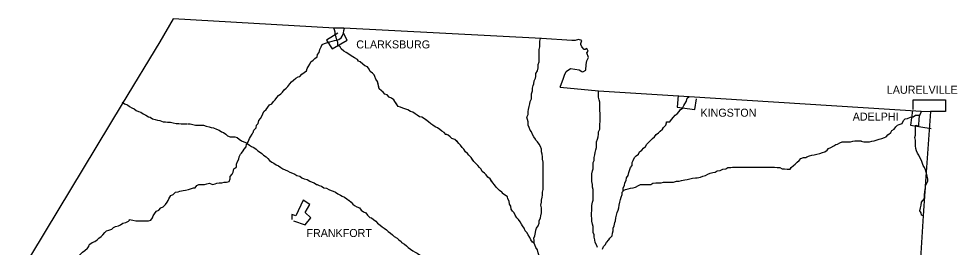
# Model space of a CAD drawing. Extents: x 0 to 34, y 0 to 22.
# Drawn here: x 4.753 to 7.039, y 19.457 to 20.014 of the extents above; entities that cross this region are included whole.
import ezdxf

# ---------------------------------------------------------------- set-up
doc = ezdxf.new("R2010")
doc.units = 0
doc.layers.add('Default', color=7, linetype='Continuous')

msp = doc.modelspace()

# ---------------------------------------------------------------- linework, layer by layer
at = {"layer": 'Default'}
for p, q in [((5.5454, 19.9346), (5.5416, 19.9382)), ((5.5509, 19.9318), (5.5454, 19.9346)), ((5.555, 19.9291), (5.5509, 19.9318)), ((5.5604, 19.925), (5.555, 19.9291)), ((5.5672, 19.9209), (5.5604, 19.925)), ((5.5713, 19.9182), (5.5672, 19.9209)), ((5.5781, 19.9141), (5.5713, 19.9182)), ((5.5809, 19.91), (5.5781, 19.9141)), ((5.585, 19.9087), (5.5809, 19.91)), ((5.5918, 19.9032), (5.585, 19.9087)), ((5.5959, 19.8991), (5.5918, 19.9032)), ((5.6027, 19.8964), (5.5959, 19.8991)), ((5.6068, 19.8909), (5.6027, 19.8964)), ((5.6095, 19.8855), (5.6068, 19.8909)), ((5.615, 19.8814), (5.6095, 19.8855)), ((5.619, 19.8773), (5.615, 19.8814)), ((5.6204, 19.8732), (5.619, 19.8773)), ((5.6231, 19.8664), (5.6204, 19.8732)), ((5.6272, 19.8609), (5.6231, 19.8664)), ((5.6313, 19.8432), (5.6272, 19.8609)), ((5.6368, 19.8378), (5.6313, 19.8432)), ((5.6409, 19.835), (5.6368, 19.8378)), ((5.645, 19.8296), (5.6409, 19.835)), ((5.6504, 19.8282), (5.645, 19.8296)), ((5.6559, 19.8228), (5.6504, 19.8282)), ((5.6613, 19.82), (5.6559, 19.8228)), ((5.6668, 19.8159), (5.6613, 19.82)), ((5.6695, 19.8118), (5.6668, 19.8159)), ((5.6777, 19.7996), (5.6695, 19.8118)), ((5.6831, 19.7982), (5.6777, 19.7996)), ((5.6886, 19.7955), (5.6831, 19.7982)), ((5.694, 19.7941), (5.6886, 19.7955)), ((5.7009, 19.7914), (5.694, 19.7941)), ((5.7077, 19.7873), (5.7009, 19.7914)), ((5.7131, 19.7859), (5.7077, 19.7873)), ((5.7186, 19.7819), (5.7131, 19.7859)), ((5.724, 19.7791), (5.7186, 19.7819)), ((5.7295, 19.775), (5.724, 19.7791)), ((5.7349, 19.7737), (5.7295, 19.775)), ((6.9416, 19.7873), (6.9416, 19.7873)), ((5.7418, 19.7696), (5.7349, 19.7737)), ((5.7513, 19.7628), (5.7418, 19.7696)), ((5.7568, 19.7573), (5.7513, 19.7628)), ((5.7622, 19.7546), (5.7568, 19.7573)), ((5.7677, 19.7505), (5.7622, 19.7546)), ((5.7731, 19.7478), (5.7677, 19.7505)), ((5.7786, 19.7437), (5.7731, 19.7478)), ((5.784, 19.7396), (5.7786, 19.7437)), ((5.7895, 19.7369), (5.784, 19.7396)), ((5.7936, 19.7314), (5.7895, 19.7369)), ((5.799, 19.73), (5.7936, 19.7314)), ((5.8045, 19.726), (5.799, 19.73)), ((5.8086, 19.7219), (5.8045, 19.726)), ((5.8154, 19.7191), (5.8086, 19.7219)), ((5.8154, 19.7191), (5.8249, 19.7096)), ((5.8249, 19.7096), (5.8154, 19.7191)), ((5.829, 19.7055), (5.8249, 19.7096)), ((5.8331, 19.7), (5.829, 19.7055)), ((5.8372, 19.696), (5.8331, 19.7)), ((5.8413, 19.6891), (5.8372, 19.696)), ((5.8467, 19.6851), (5.8413, 19.6891)), ((5.8495, 19.681), (5.8467, 19.6851)), ((5.8549, 19.6755), (5.8495, 19.681)), ((5.8617, 19.666), (5.8549, 19.6755)), ((5.8658, 19.6619), (5.8617, 19.666)), ((5.8713, 19.6564), (5.8658, 19.6619)), ((5.8754, 19.651), (5.8713, 19.6564)), ((5.8795, 19.6469), (5.8754, 19.651)), ((5.8822, 19.6414), (5.8795, 19.6469)), ((5.8876, 19.6373), (5.8822, 19.6414)), ((5.8917, 19.6332), (5.8876, 19.6373)), ((5.8958, 19.6278), (5.8917, 19.6332)), ((5.9013, 19.6237), (5.8958, 19.6278)), ((5.9081, 19.6142), (5.9013, 19.6237)), ((5.9122, 19.6087), (5.9081, 19.6142)), ((5.9163, 19.6032), (5.9122, 19.6087)), ((5.9204, 19.5992), (5.9163, 19.6032)), ((5.9245, 19.5951), (5.9204, 19.5992)), ((5.9299, 19.591), (5.9245, 19.5951)), ((5.9313, 19.5882), (5.9299, 19.591)), ((5.9381, 19.5842), (5.9313, 19.5882)), ((5.9435, 19.5801), (5.9381, 19.5842)), ((5.9449, 19.5746), (5.9435, 19.5801)), ((5.9476, 19.5692), (5.9449, 19.5746)), ((5.949, 19.5623), (5.9476, 19.5692)), ((5.9517, 19.5569), (5.949, 19.5623)), ((5.9531, 19.5501), (5.9517, 19.5569)), ((5.9558, 19.5446), (5.9531, 19.5501))]:
    msp.add_line(p, q, dxfattribs=at)
for points in [[(5.1296, 20.0136), (5.0969, 19.9577), (5.0055, 19.8064), (4.7533, 19.3892)], [(6.0717, 19.8473), (6.0799, 19.8691), (6.0826, 19.8759), (6.0867, 19.8855), (6.0976, 19.8923), (6.1181, 19.8896), (6.1249, 19.8855), (6.1276, 19.8841), (6.1344, 19.8882), (6.1358, 19.9018), (6.1371, 19.9114), (6.1412, 19.9196), (6.1371, 19.9305), (6.1399, 19.9346), (6.1371, 19.9414), (6.1331, 19.9386), (6.1303, 19.9386), (6.1249, 19.9455), (6.1221, 19.9509), (6.1221, 19.9536), (6.1249, 19.9605), (6.1167, 19.9632), (6.1085, 19.9605), (6.1003, 19.9605), (6.0267, 19.9659), (5.5454, 19.9905), (5.5222, 19.9905), (5.1296, 20.0136)], [(5.5277, 19.9618), (5.5263, 19.9686), (5.5236, 19.9755), (5.5236, 19.9809), (5.5222, 19.9864), (5.5209, 19.9905)], [(5.5277, 19.9618), (5.5331, 19.9632), (5.5386, 19.9673), (5.5413, 19.9714), (5.5441, 19.9782), (5.5454, 19.985), (5.5468, 19.9905)], [(5.4282, 19.8691), (5.4336, 19.8718), (5.4377, 19.8732), (5.4432, 19.8787), (5.4486, 19.8827), (5.4541, 19.8868), (5.4554, 19.8923), (5.4582, 19.8964), (5.4623, 19.9032), (5.465, 19.9087), (5.4704, 19.9127), (5.4745, 19.9168), (5.48, 19.9209), (5.4813, 19.9264), (5.4854, 19.9318), (5.4868, 19.9386), (5.4895, 19.9455), (5.4922, 19.9509), (5.4977, 19.9536), (5.5032, 19.955), (5.5113, 19.9577), (5.5168, 19.9591), (5.5222, 19.9605), (5.5277, 19.9618), (5.5277, 19.9618)], [(5.5304, 19.9782), (5.5032, 19.9618), (5.5168, 19.94), (5.5536, 19.9618), (5.5441, 19.9782)], [(5.5781, 19.9141), (5.5713, 19.9182), (5.5672, 19.9209), (5.5604, 19.925), (5.555, 19.9291), (5.5509, 19.9318), (5.5454, 19.9346), (5.5386, 19.94), (5.5359, 19.9455), (5.5304, 19.9496), (5.5304, 19.9564), (5.5277, 19.9618)], [(6.0185, 19.895), (6.0185, 19.9018), (6.0213, 19.9087), (6.0213, 19.9127), (6.0213, 19.9209), (6.0213, 19.9264), (6.0213, 19.9346), (6.0213, 19.9386), (6.0226, 19.9455), (6.0226, 19.9523), (6.0226, 19.9591), (6.024, 19.9659), (6.024, 19.9659)], [(5.619, 19.8773), (5.615, 19.8814), (5.6095, 19.8855), (5.6068, 19.8909), (5.6027, 19.8964), (5.5959, 19.8991), (5.5918, 19.9032), (5.585, 19.9087), (5.5809, 19.91), (5.5781, 19.9141)], [(6.0117, 19.7205), (6.0076, 19.726), (6.0049, 19.7314), (6.0022, 19.7382), (5.9994, 19.7423), (5.9967, 19.7491), (5.994, 19.7546), (5.994, 19.7628), (5.9926, 19.7682), (5.9913, 19.7737), (5.994, 19.7805), (5.994, 19.7873), (5.9953, 19.7928), (5.9967, 19.7996), (5.9981, 19.8064), (5.9994, 19.8118), (6.0022, 19.8187), (6.0022, 19.8241), (6.0022, 19.8309), (6.0049, 19.8378), (6.0049, 19.8446), (6.0063, 19.8514), (6.0076, 19.8555), (6.009, 19.8623), (6.0117, 19.8691), (6.0131, 19.8732), (6.0131, 19.88), (6.0172, 19.8868), (6.0185, 19.8937), (6.0185, 19.895)], [(5.3505, 19.7873), (5.3559, 19.7928), (5.36, 19.7982), (5.3641, 19.8037), (5.3695, 19.8064), (5.3736, 19.8118), (5.3777, 19.8159), (5.3818, 19.8214), (5.3859, 19.8268), (5.3914, 19.8309), (5.3954, 19.835), (5.3995, 19.8405), (5.405, 19.8446), (5.4091, 19.8487), (5.4132, 19.8555), (5.4173, 19.8596), (5.4227, 19.8637), (5.4282, 19.8691), (5.4282, 19.8691)], [(5.645, 19.8296), (5.6409, 19.835), (5.6368, 19.8378), (5.6313, 19.8432), (5.63, 19.8487), (5.6286, 19.8555), (5.6272, 19.8609), (5.6231, 19.8664), (5.6204, 19.8732), (5.619, 19.8773)], [(6.0717, 19.8473), (6.1658, 19.8378), (6.3867, 19.8241), (6.9511, 19.7887), (6.9743, 19.7873)], [(5.7131, 19.7859), (5.7077, 19.7873), (5.7009, 19.7914), (5.694, 19.7941), (5.6886, 19.7955), (5.6831, 19.7982), (5.6777, 19.7996), (5.6736, 19.8064), (5.6695, 19.8118), (5.6668, 19.8159), (5.6613, 19.82), (5.6559, 19.8228), (5.6504, 19.8282), (5.645, 19.8296), (5.645, 19.8296)], [(6.1631, 19.456), (6.1603, 19.4628), (6.1576, 19.4683), (6.1562, 19.4751), (6.1549, 19.4819), (6.1549, 19.4874), (6.1521, 19.4928), (6.1521, 19.501), (6.1521, 19.5078), (6.1508, 19.5133), (6.1494, 19.5201), (6.1494, 19.5269), (6.1481, 19.5337), (6.1481, 19.5405), (6.1494, 19.546), (6.1494, 19.5528), (6.1494, 19.5583), (6.1508, 19.5664), (6.1521, 19.5719), (6.1521, 19.5787), (6.1521, 19.5842), (6.1521, 19.591), (6.1521, 19.5978), (6.1508, 19.6032), (6.1508, 19.6101), (6.1494, 19.6169), (6.1494, 19.6237), (6.1494, 19.6305), (6.1494, 19.636), (6.1508, 19.6428), (6.1521, 19.6482), (6.1521, 19.6564), (6.1521, 19.6632), (6.1549, 19.6687), (6.1549, 19.6755), (6.1562, 19.6823), (6.1576, 19.6878), (6.159, 19.6946), (6.1603, 19.7), (6.1603, 19.7082), (6.1603, 19.7137), (6.1631, 19.7205), (6.1644, 19.726), (6.1658, 19.7328), (6.1658, 19.7382), (6.1685, 19.745), (6.1685, 19.7505), (6.1685, 19.7573), (6.1699, 19.7628), (6.1699, 19.7709), (6.1699, 19.7764), (6.1699, 19.7832), (6.1685, 19.79), (6.1685, 19.7969), (6.1685, 19.8037), (6.1685, 19.8105), (6.1671, 19.8159), (6.1658, 19.8228), (6.1658, 19.8296), (6.1658, 19.835), (6.1658, 19.8364), (6.1658, 19.8378)], [(6.3321, 19.7628), (6.3389, 19.7628), (6.343, 19.7682), (6.3485, 19.7737), (6.3526, 19.7791), (6.3567, 19.7819), (6.3621, 19.7873), (6.3648, 19.7914), (6.3703, 19.7955), (6.373, 19.8023), (6.3757, 19.8064), (6.3798, 19.8132), (6.3812, 19.82), (6.3867, 19.8241), (6.3867, 19.8241)], [(6.3594, 19.8268), (6.3567, 19.7982), (6.4003, 19.7928), (6.4044, 19.8187)], [(5.0055, 19.8105), (5.011, 19.8064), (5.0178, 19.8037), (5.0232, 19.7996), (5.0287, 19.7969), (5.0341, 19.7941), (5.0396, 19.79), (5.045, 19.7873), (5.0505, 19.7859), (5.056, 19.7819), (5.0628, 19.7791), (5.0696, 19.775), (5.0737, 19.7737), (5.0791, 19.7696), (5.0859, 19.7682), (5.0914, 19.7669), (5.0969, 19.7655), (5.105, 19.7628), (5.1105, 19.7628), (5.1159, 19.7614), (5.1228, 19.7614), (5.1296, 19.76), (5.1364, 19.7587), (5.1432, 19.7587), (5.1487, 19.7573), (5.1555, 19.7573), (5.1623, 19.7573), (5.1637, 19.7573)], [(6.932, 19.7928), (6.932, 19.8159), (7.0111, 19.8159), (7.0111, 19.7873), (6.9743, 19.7873)], [(5.3245, 19.7369), (5.3259, 19.7423), (5.3314, 19.7478), (5.3327, 19.7546), (5.3368, 19.7587), (5.3382, 19.7655), (5.3423, 19.7709), (5.345, 19.7764), (5.3477, 19.7819), (5.3505, 19.7873), (5.3505, 19.7873)], [(5.7936, 19.7314), (5.7895, 19.7369), (5.784, 19.7396), (5.7786, 19.7437), (5.7731, 19.7478), (5.7677, 19.7505), (5.7622, 19.7546), (5.7568, 19.7573), (5.7513, 19.7628), (5.7472, 19.7655), (5.7418, 19.7696), (5.7349, 19.7737), (5.7295, 19.775), (5.724, 19.7791), (5.7186, 19.7819), (5.7131, 19.7859), (5.7131, 19.7859)], [(6.872, 19.7314), (6.8775, 19.7369), (6.8802, 19.741), (6.8857, 19.745), (6.8898, 19.7505), (6.8938, 19.7546), (6.8979, 19.7559), (6.9048, 19.7587), (6.9088, 19.7655), (6.9129, 19.7696), (6.9184, 19.7709), (6.9252, 19.7737), (6.932, 19.775), (6.9375, 19.7791), (6.9429, 19.7791), (6.9484, 19.7791)], [(6.9307, 19.79), (6.9252, 19.7546), (6.9756, 19.7464)], [(6.9634, 19.6401), (6.962, 19.6455), (6.9593, 19.651), (6.9566, 19.6564), (6.9538, 19.6632), (6.9525, 19.6687), (6.9484, 19.6755), (6.9457, 19.681), (6.9429, 19.6864), (6.9402, 19.6919), (6.9388, 19.6973), (6.9375, 19.7041), (6.9375, 19.711), (6.9375, 19.7178), (6.9361, 19.7246), (6.9375, 19.73), (6.9375, 19.7369), (6.9375, 19.7423), (6.9375, 19.7491), (6.9388, 19.7546), (6.9457, 19.7519), (6.9457, 19.7573), (6.947, 19.7655), (6.947, 19.7709), (6.9484, 19.7791), (6.9484, 19.7791)], [(6.9484, 19.7791), (6.9511, 19.7859), (6.9511, 19.7887)], [(6.9743, 19.7873), (6.9634, 19.6401), (6.9607, 19.5937), (6.9566, 19.5337)], [(5.165, 19.7573), (5.1705, 19.7573), (5.1773, 19.7559), (5.1841, 19.7546), (5.1896, 19.7546), (5.1977, 19.7546), (5.2032, 19.7546), (5.21, 19.7519), (5.2168, 19.7505), (5.2223, 19.7491), (5.2277, 19.7478), (5.2346, 19.745), (5.2414, 19.7423), (5.2468, 19.7382), (5.2523, 19.7369), (5.2577, 19.7328)], [(6.2258, 19.5951), (6.2258, 19.6019), (6.2285, 19.6073), (6.2299, 19.6142), (6.2326, 19.6196), (6.2339, 19.6264), (6.238, 19.6319), (6.2394, 19.6387), (6.2408, 19.6441), (6.2435, 19.651), (6.2476, 19.6564), (6.2476, 19.6632), (6.2503, 19.6687), (6.253, 19.6755), (6.2571, 19.6796), (6.2626, 19.6837), (6.2653, 19.6891), (6.2708, 19.6932), (6.2749, 19.6987), (6.2803, 19.7028), (6.283, 19.7082), (6.2885, 19.7137), (6.2926, 19.7178), (6.2967, 19.7219), (6.3021, 19.726), (6.3062, 19.7314), (6.3117, 19.7355), (6.3158, 19.7396), (6.3212, 19.745), (6.3239, 19.7491), (6.3294, 19.7546), (6.3308, 19.76), (6.3308, 19.7628), (6.3321, 19.7628)], [(5.2577, 19.7328), (5.2618, 19.7287), (5.2686, 19.726), (5.2741, 19.726), (5.2796, 19.726), (5.285, 19.7246), (5.2905, 19.7205), (5.2959, 19.7164), (5.3014, 19.7137), (5.3082, 19.711), (5.3095, 19.7096)], [(5.3095, 19.7096), (5.3123, 19.7137), (5.315, 19.7219), (5.3177, 19.726), (5.3218, 19.7328), (5.3232, 19.7355), (5.3245, 19.7369)], [(5.9299, 19.591), (5.9245, 19.5951), (5.9204, 19.5992), (5.9163, 19.6032), (5.9122, 19.6087), (5.9081, 19.6142), (5.904, 19.6182), (5.9013, 19.6237), (5.8958, 19.6278), (5.8917, 19.6332), (5.8876, 19.6373), (5.8822, 19.6414), (5.8795, 19.6469), (5.8754, 19.651), (5.8713, 19.6564), (5.8658, 19.6619), (5.8617, 19.666), (5.8576, 19.6714), (5.8549, 19.6755), (5.8495, 19.681), (5.8467, 19.6851), (5.8413, 19.6891), (5.8372, 19.696), (5.8331, 19.7), (5.829, 19.7055), (5.8249, 19.7096), (5.8222, 19.7137), (5.8154, 19.7191), (5.8086, 19.7219), (5.8045, 19.726), (5.799, 19.73), (5.7963, 19.7314), (5.7936, 19.7314)], [(6.8052, 19.715), (6.812, 19.7137), (6.8189, 19.7137), (6.8257, 19.7137), (6.8311, 19.715), (6.8366, 19.7164), (6.842, 19.7178), (6.8489, 19.7205), (6.8557, 19.7219), (6.8625, 19.7246), (6.8666, 19.726), (6.8707, 19.7314), (6.872, 19.7314)], [(5.2959, 19.6864), (5.3, 19.6919), (5.3027, 19.696), (5.3068, 19.7014), (5.3082, 19.7082), (5.3095, 19.7096)], [(5.3095, 19.7096), (5.315, 19.7055), (5.3205, 19.7028), (5.3259, 19.7), (5.3314, 19.696), (5.3355, 19.6919), (5.3395, 19.6891), (5.345, 19.6851), (5.3491, 19.681), (5.3559, 19.6769), (5.36, 19.6728), (5.3641, 19.6687), (5.3695, 19.6646), (5.375, 19.6619), (5.3804, 19.6578), (5.3859, 19.6551), (5.3914, 19.651), (5.3968, 19.6482), (5.4023, 19.6455), (5.4077, 19.6428), (5.4132, 19.6401), (5.42, 19.6373), (5.4254, 19.6346), (5.4309, 19.6319), (5.4377, 19.6305), (5.4432, 19.6264), (5.4486, 19.6237), (5.4554, 19.6223), (5.4623, 19.6182), (5.4677, 19.6155), (5.4732, 19.6142), (5.4786, 19.6101), (5.48, 19.6101)], [(6.0308, 19.6073), (6.0308, 19.6142), (6.0308, 19.621), (6.0308, 19.6264), (6.0308, 19.6332), (6.0308, 19.6401), (6.0308, 19.6455), (6.0308, 19.6523), (6.0308, 19.6591), (6.0308, 19.6646), (6.0294, 19.6714), (6.0294, 19.6769), (6.0281, 19.6837), (6.0267, 19.6891), (6.0267, 19.696), (6.024, 19.7028), (6.0213, 19.7082), (6.0172, 19.7137), (6.0131, 19.7178), (6.0117, 19.7205)], [(6.673, 19.6769), (6.6798, 19.6796), (6.6852, 19.681), (6.6907, 19.6823), (6.6975, 19.6837), (6.7043, 19.6851), (6.7111, 19.6878), (6.7166, 19.6891), (6.7221, 19.6932), (6.7261, 19.6973), (6.7316, 19.7), (6.7384, 19.7041), (6.7439, 19.7069), (6.748, 19.7082), (6.7534, 19.711), (6.7589, 19.7137), (6.7657, 19.7137), (6.7725, 19.7137), (6.7793, 19.7137), (6.7848, 19.715), (6.7902, 19.7164), (6.7984, 19.7164), (6.8052, 19.7164), (6.8052, 19.715)], [(5.2836, 19.6523), (5.2836, 19.6591), (5.2864, 19.666), (5.2891, 19.6714), (5.2905, 19.6769), (5.2932, 19.6837), (5.2959, 19.6864)], [(6.493, 19.6523), (6.4985, 19.6523), (6.5039, 19.6523), (6.5107, 19.6523), (6.5175, 19.6523), (6.5244, 19.6523), (6.5312, 19.6523), (6.538, 19.6523), (6.5434, 19.6523), (6.5516, 19.6523), (6.5571, 19.6523), (6.5639, 19.6523), (6.5693, 19.6523), (6.5762, 19.6523), (6.583, 19.6523), (6.5884, 19.6523), (6.5939, 19.6523), (6.6007, 19.651), (6.6075, 19.651), (6.613, 19.6482), (6.6184, 19.6482), (6.6252, 19.6469), (6.6321, 19.6469), (6.6348, 19.651), (6.6402, 19.6564), (6.6443, 19.6591), (6.6498, 19.6646), (6.6539, 19.6687), (6.658, 19.6728), (6.6648, 19.6755), (6.6702, 19.6755), (6.673, 19.6769)], [(5.2482, 19.6142), (5.2536, 19.6155), (5.2591, 19.6155), (5.2659, 19.6169), (5.2686, 19.6237), (5.2686, 19.6291), (5.2727, 19.6346), (5.2755, 19.6401), (5.2768, 19.6482), (5.2823, 19.651), (5.2836, 19.6523)], [(6.2258, 19.5951), (6.2312, 19.5978), (6.238, 19.5992), (6.2435, 19.6005), (6.2503, 19.6019), (6.2558, 19.6032), (6.2626, 19.6073), (6.268, 19.6101), (6.2735, 19.6101), (6.2803, 19.6101), (6.2844, 19.6101), (6.2926, 19.6101), (6.298, 19.6128), (6.3048, 19.6142), (6.3117, 19.6142), (6.3185, 19.6142), (6.3239, 19.6155), (6.3308, 19.6155), (6.3376, 19.6155), (6.343, 19.6155), (6.3485, 19.6155), (6.3553, 19.6182), (6.3621, 19.6182), (6.3676, 19.6196), (6.3757, 19.621), (6.3812, 19.6223), (6.388, 19.6237), (6.3948, 19.6251), (6.4016, 19.6264), (6.4057, 19.6264), (6.4139, 19.6278), (6.4194, 19.6305), (6.4262, 19.6319), (6.4316, 19.6346), (6.4371, 19.6373), (6.4439, 19.6387), (6.4494, 19.6401), (6.4548, 19.6428), (6.4616, 19.6441), (6.4685, 19.6469), (6.4753, 19.6482), (6.4807, 19.651), (6.4875, 19.651), (6.4916, 19.6523), (6.493, 19.6523)], [(6.9607, 19.5937), (6.962, 19.5992), (6.962, 19.6073), (6.9647, 19.6114), (6.9675, 19.6182), (6.9675, 19.6237), (6.9661, 19.6305), (6.9647, 19.6373), (6.9634, 19.6401), (6.9634, 19.6401)], [(5.1187, 19.5746), (5.1214, 19.5787), (5.1241, 19.5828), (5.1296, 19.5855), (5.135, 19.591), (5.1418, 19.5923), (5.1459, 19.5937), (5.1541, 19.5951), (5.1596, 19.5964), (5.1664, 19.5978), (5.1718, 19.5992), (5.1787, 19.6019), (5.1828, 19.6019), (5.1828, 19.6019)], [(5.1828, 19.6019), (5.1868, 19.6073), (5.1923, 19.6101), (5.2005, 19.6101), (5.2059, 19.6101), (5.2114, 19.6114), (5.2182, 19.6128), (5.225, 19.6101), (5.2318, 19.6114), (5.2359, 19.6128), (5.2414, 19.6142), (5.2468, 19.6142), (5.2482, 19.6142)], [(5.48, 19.6101), (5.4854, 19.6073), (5.4909, 19.606), (5.4963, 19.6019), (5.5032, 19.6005), (5.5086, 19.5978), (5.5141, 19.5951), (5.5195, 19.5937), (5.525, 19.591), (5.5304, 19.5869), (5.5372, 19.5842), (5.5413, 19.5814), (5.5468, 19.5787), (5.5522, 19.5746), (5.5563, 19.5719), (5.5577, 19.5719)], [(6.009, 19.4669), (6.009, 19.4737), (6.0076, 19.4792), (6.0103, 19.4846), (6.0117, 19.4928), (6.0131, 19.4983), (6.0144, 19.5037), (6.0185, 19.5092), (6.0213, 19.516), (6.0213, 19.5214), (6.024, 19.5283), (6.0253, 19.5337), (6.0267, 19.5405), (6.0267, 19.546), (6.0267, 19.5528), (6.0253, 19.5596), (6.0267, 19.5664), (6.0267, 19.5719), (6.0281, 19.5787), (6.0294, 19.5842), (6.0294, 19.591), (6.0308, 19.5978), (6.0308, 19.6019), (6.0308, 19.6073)], [(6.1753, 19.4519), (6.178, 19.4587), (6.1821, 19.4628), (6.1849, 19.4683), (6.1903, 19.4751), (6.193, 19.4792), (6.1985, 19.4846), (6.1999, 19.4914), (6.2012, 19.4969), (6.2012, 19.5037), (6.204, 19.5092), (6.2053, 19.5173), (6.2067, 19.5214), (6.208, 19.5283), (6.2094, 19.5351), (6.2108, 19.5419), (6.2135, 19.5473), (6.2149, 19.5528), (6.2162, 19.5596), (6.2176, 19.5664), (6.219, 19.5732), (6.2203, 19.5787), (6.223, 19.5855), (6.223, 19.591), (6.2258, 19.5937), (6.2258, 19.5951)], [(6.9566, 19.5337), (6.9525, 19.5351), (6.9511, 19.5405), (6.9484, 19.546), (6.9497, 19.5528), (6.9511, 19.5596), (6.9525, 19.5664), (6.9552, 19.5705), (6.9593, 19.576), (6.9593, 19.5814), (6.9593, 19.5855), (6.9607, 19.591), (6.9607, 19.5937)], [(5.0232, 19.5242), (5.0314, 19.5228), (5.0382, 19.5214), (5.045, 19.5214), (5.0505, 19.5214), (5.056, 19.5214), (5.0641, 19.5214), (5.0696, 19.5214), (5.075, 19.5228), (5.0791, 19.5283), (5.0805, 19.5337), (5.0859, 19.5405), (5.0887, 19.5446), (5.0941, 19.5473), (5.0996, 19.5528), (5.105, 19.5555), (5.1105, 19.561), (5.1146, 19.5664), (5.1173, 19.5705), (5.1187, 19.5746)], [(5.4227, 19.5214), (5.4513, 19.5119), (5.465, 19.5283), (5.4513, 19.5419), (5.4623, 19.561), (5.4459, 19.5719), (5.4282, 19.5337), (5.4186, 19.5364), (5.4186, 19.5242)], [(5.5577, 19.5719), (5.5631, 19.5664), (5.5672, 19.5623), (5.5713, 19.5583), (5.5768, 19.5555), (5.5836, 19.5528), (5.5877, 19.5473), (5.5931, 19.5433), (5.5986, 19.5405), (5.6027, 19.5351), (5.6081, 19.5296), (5.6122, 19.5283), (5.6177, 19.5242), (5.6231, 19.5201), (5.6272, 19.516), (5.634, 19.5105), (5.6381, 19.5064), (5.6436, 19.5037), (5.649, 19.4996), (5.6531, 19.4955), (5.6586, 19.4914), (5.664, 19.4874), (5.6681, 19.4833), (5.6749, 19.4792), (5.679, 19.4751), (5.6845, 19.471), (5.6859, 19.4683), (5.6859, 19.4683)], [(6.009, 19.4669), (6.0049, 19.4696), (6.0008, 19.4751), (5.9981, 19.4805), (5.994, 19.4874), (5.9913, 19.4928), (5.9872, 19.4969), (5.9844, 19.5037), (5.9804, 19.5092), (5.9776, 19.5133), (5.9749, 19.5187), (5.9708, 19.5242), (5.9667, 19.5283), (5.9626, 19.5351), (5.9599, 19.5405), (5.9558, 19.5446), (5.9531, 19.5501), (5.9517, 19.5569), (5.949, 19.5623), (5.9476, 19.5692), (5.9449, 19.5746), (5.9435, 19.5801), (5.9381, 19.5842), (5.9313, 19.5882), (5.9313, 19.5896), (5.9299, 19.591)], [(4.9264, 19.4642), (4.9319, 19.4683), (4.9387, 19.471), (4.9442, 19.4751), (4.9482, 19.4792), (4.9537, 19.4833), (4.9578, 19.4874), (4.9632, 19.4928), (4.9673, 19.4969), (4.9728, 19.4983), (4.9796, 19.501), (4.9837, 19.5051), (4.9891, 19.5078), (4.996, 19.5092), (5.0014, 19.5119), (5.0069, 19.516), (5.0137, 19.5173), (5.0205, 19.5201), (5.0232, 19.5228), (5.0232, 19.5242), (5.0232, 19.5242)], [(6.9566, 19.5337), (6.9457, 19.3646), (6.9197, 18.9774), (6.9088, 18.8056), (6.8925, 18.6093)], [(4.8364, 19.381), (4.8405, 19.3865), (4.8473, 19.3892), (4.8514, 19.3946), (4.8569, 19.3987), (4.8596, 19.4028), (4.8664, 19.4069), (4.8705, 19.411), (4.876, 19.4151), (4.8814, 19.4192), (4.8842, 19.4233), (4.891, 19.4287), (4.8951, 19.4315), (4.9005, 19.4369), (4.906, 19.4424), (4.9087, 19.4451), (4.9142, 19.4492), (4.921, 19.4546), (4.9237, 19.4587), (4.9251, 19.4628), (4.9264, 19.4642)], [(5.6859, 19.4683), (5.6927, 19.4642), (5.6981, 19.4601), (5.7022, 19.456), (5.7077, 19.4519), (5.7131, 19.4478), (5.7186, 19.4451), (5.724, 19.4424), (5.7295, 19.4383), (5.7349, 19.4355), (5.7404, 19.4315), (5.7458, 19.4301), (5.7513, 19.4274), (5.7568, 19.426), (5.7622, 19.4233), (5.769, 19.4205), (5.7745, 19.4192), (5.7813, 19.4178), (5.7881, 19.4178), (5.7922, 19.4165), (5.7922, 19.4165)], [(6.024, 19.4055), (6.0226, 19.4137), (6.0213, 19.4192), (6.0213, 19.426), (6.0199, 19.4315), (6.0199, 19.4383), (6.0185, 19.4437), (6.0172, 19.4505), (6.0131, 19.456), (6.0103, 19.4628), (6.009, 19.4669), (6.009, 19.4669)]]:
    msp.add_lwpolyline(points, dxfattribs=at)

# ---------------------------------------------------------------- texts
for s, height, p in [('CLARKSBURG', 0.0195, (5.5754, 19.9414)), ('LAURELVILLE', 0.019502, (6.8679, 19.8309)), ('KINGSTON', 0.0195, (6.4139, 19.775)), ('ADELPHI', 0.0195, (6.7848, 19.7655)), ('FRANKFORT', 0.0195, (5.4541, 19.4819))]:
    msp.add_text(s, height=height, dxfattribs=at).set_placement(p)

doc.saveas('drawing.dxf')
